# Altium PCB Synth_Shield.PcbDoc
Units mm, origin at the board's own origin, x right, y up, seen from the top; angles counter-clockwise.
Board outline 142 x 65.3 mm, 2 copper layers (TOP, BOTTOM), stack 1.5 mm thick; 26 components, 14 nets, 113 pads, 0 vias.
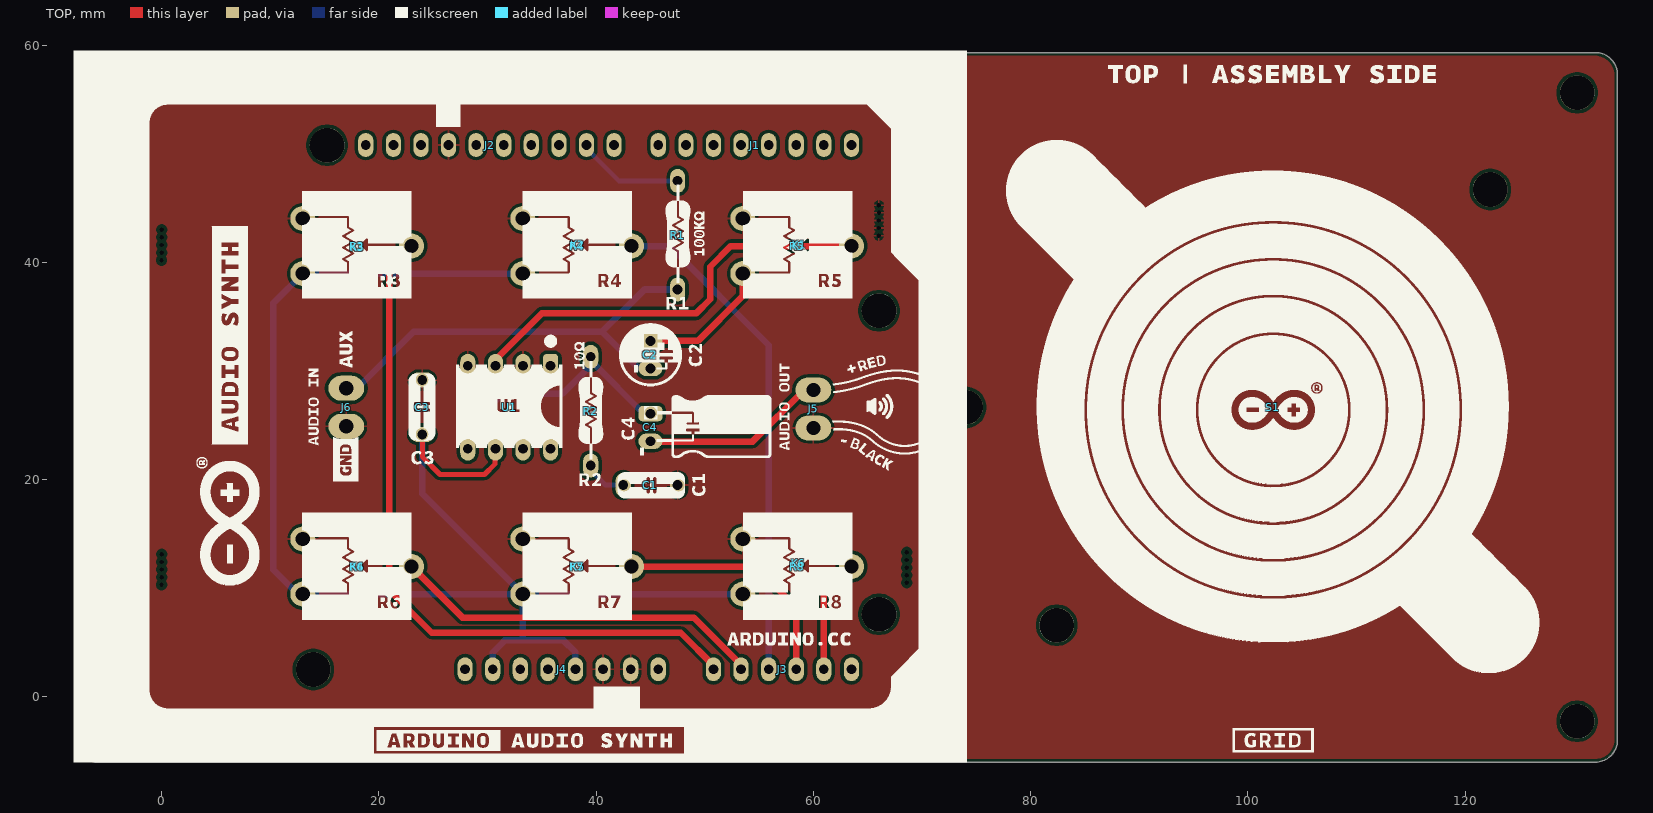
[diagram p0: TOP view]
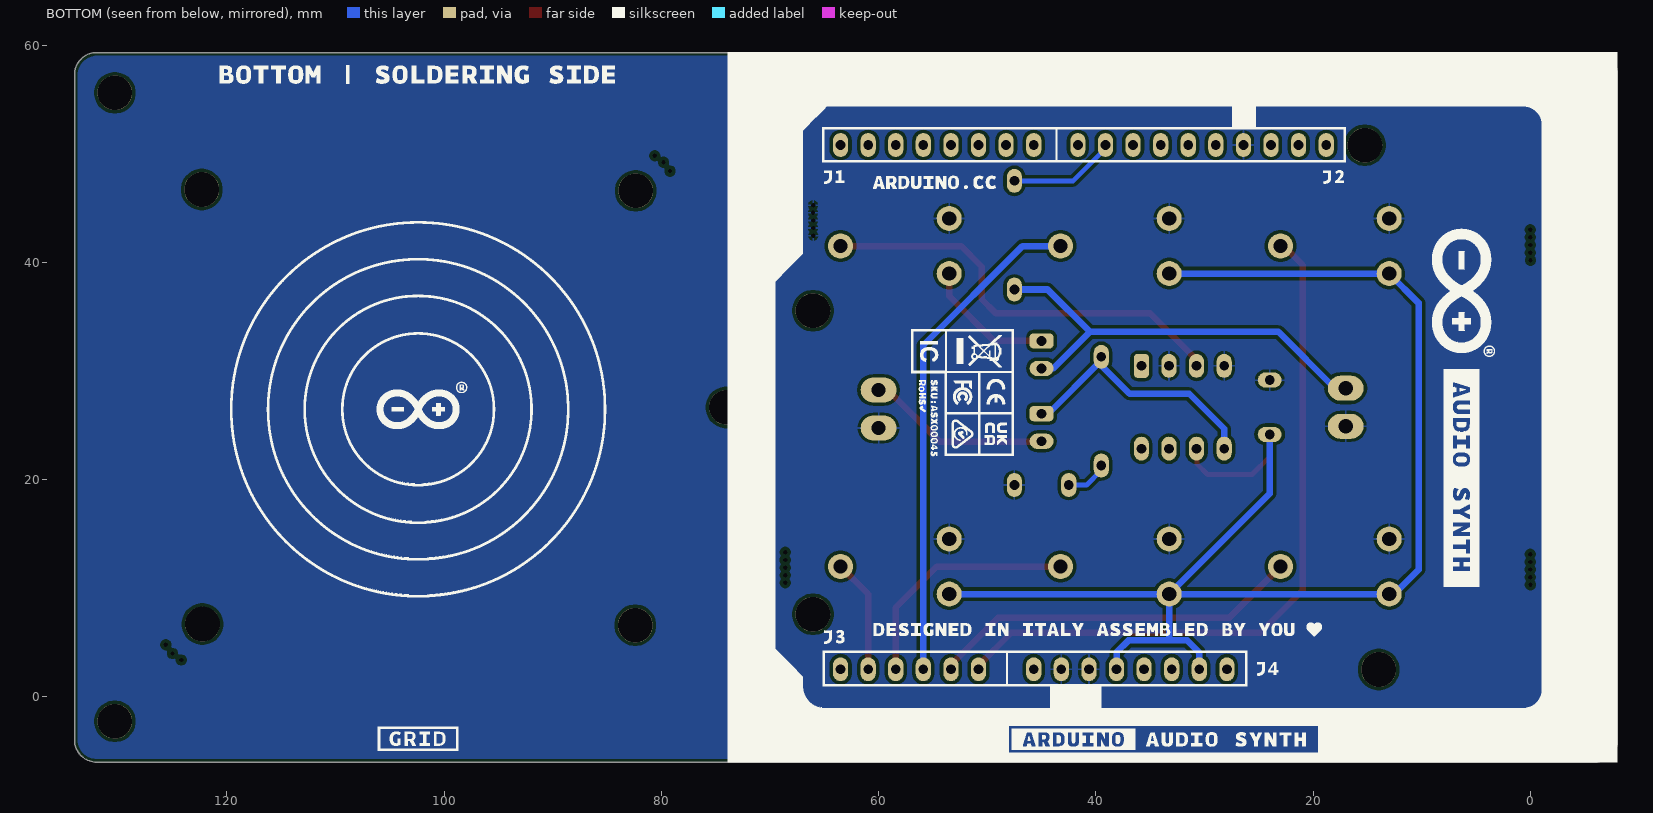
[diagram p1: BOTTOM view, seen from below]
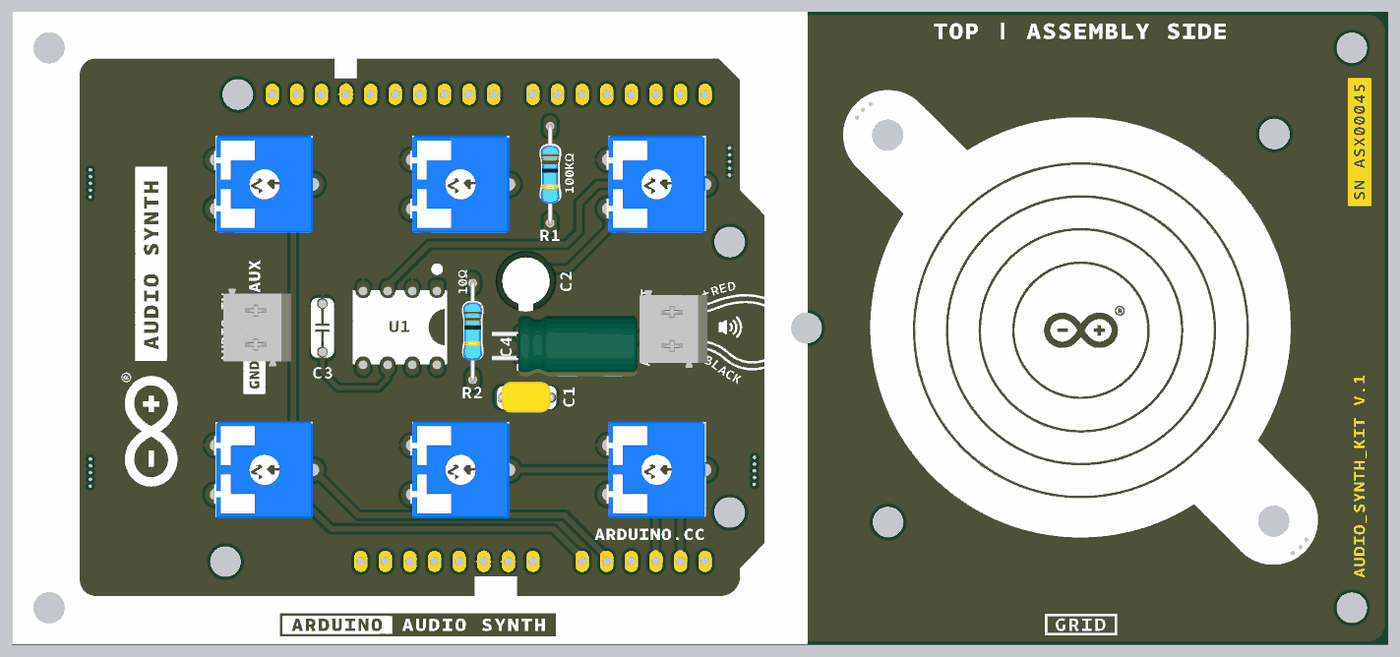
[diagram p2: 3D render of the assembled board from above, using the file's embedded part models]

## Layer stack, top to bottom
Top Solder: solder mask 0.0102, Solder Resist, Dk 3.5
TOP: signal copper 0.018
Dielectric2: core 1.464, FR-4, Dk 4.8
BOTTOM: signal copper 0.018
Bottom Solder: solder mask 0.0102, Solder Resist, Dk 3.5

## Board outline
-6,-6 cw(c-6,-4) -8,-4 -8,57.3 cw(c-6,57.3) -6,59.3 132,59.3 cw(c132,57.3) 134,57.3 134,-4 cw(c132,-4) 132,-6

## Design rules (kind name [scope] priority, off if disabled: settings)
BoardOutlineClearance Silks [(OnLayer('Top Overlay') OR OnLayer('Bottom Overlay'))] p1: gap=0 ignorepadtopadclearanceinfootprint=FALSE
BoardOutlineClearance [All] p2: gap=0.3 ignorepadtopadclearanceinfootprint=FALSE
Clearance COPPER_0.3mm [All] p1: gap=0.127 ignorepadtopadclearanceinfootprint=FALSE except(0.3: Arc-Fill Arc-Poly Arc-Region Track-Fill Track-Poly Track-Region SMDPad-Fill SMDPad-Poly SMDPad-Region THPad-Fill THPad-Poly THPad-Region Via-Fill Via-Poly Via-Region Fill-Fill Fill-Poly Fill-Region Poly-Poly Poly-Region Region-Region)
Clearance "Generic clearance 0.127mm" [All] p2: gap=0.127 ignorepadtopadclearanceinfootprint=FALSE
ComponentClearance [All] p1: gap=0.2 collisioncheckmode=3 verticalgap=0 showdistances=TRUE
DiffPairsRouting USB [InDifferentialPairClass('USB')] p1: maxlimit=0.15 minlimit=0.15 mostfreqgap=0.15 toplayer_minwidth=0.15 toplayer_maxwidth=0.21 toplayer_prefwidth=0.2 bottomlayer_minwidth=0.15 bottomlayer_maxwidth=0.21 bottomlayer_prefwidth=0.2 impedanceprofiledriven=TRUE impedanceprofileid={E6B00C31-4C8E-439C-824F-D2B2CDC26F9C} impedanceprofilevalue=90.000000 maxuncoupledlength=12.7
Height [All] p1: minheight=0 maxheight=30 prefheight=12.7
HoleSize [All] p1: absolutevalues=TRUE maxlimit=30 minlimit=0.3 maxpercent=80.000 minpercent=20.000
HoleToHoleClearance [All] p1: gap=0.25 allowstackedmicrovias=FALSE
MinimumAnnularRing [All] p1: minimumring=0.15
PlaneConnect [All] p1: pad.planeconnectstyle=Relief pad.reliefexpansion=0.508 pad.reliefentries=4 pad.reliefconductorwidth=0.254 pad.reliefairgap=0.254 via.planeconnectstyle=Direct via.reliefexpansion=0.508 via.reliefentries=4 via.reliefconductorwidth=0.254 via.reliefairgap=0.254
PolygonConnect [All] p1: thpad.connectstyle=Relief thpad.reliefconductorwidth=0.2 thpad.reliefentries=4 thpad.polygonreliefangle="90 Angle" thpad.airgapwidth=0.254 smdpad.connectstyle=Relief smdpad.reliefconductorwidth=0.2 smdpad.reliefentries=4 smdpad.polygonreliefangle="90 Angle" smdpad.airgapwidth=0.254 via.connectstyle=Direct via.reliefconductorwidth=0.254 via.reliefentries=4 via.polygonreliefangle="90 Angle" via.airgapwidth=0.254
RoomDefinition Synth_Audio_KIT [InComponentClass('Synth_Audio_KIT')] p1: confinementstyle=ConfineIn formatcopy=TRUE lockcomponents=FALSE outline -14.979,-6.4 195.1,-6.4 195.1,62.4 -14.979,62.4
RoutingVias StandardVias [All] p1: holewidth=0.3 width=0.6 viastyle="Through Hole" minholewidth=0.3 minwidth=0.6 maxholewidth=0.3 maxwidth=0.6
SMDToCorner [All] p1: distance=39370
SilkToSilkClearance [All] p1: silktosilkclearance=0.2
SilkToSolderMaskClearance [IsPad] p1: minsilkscreentomaskgap=0.15 clearancetoexposedcopper=TRUE
SolderMaskExpansion VIAtented [IsVia] p1: expansion=0.102 istentingtop=TRUE
SolderMaskExpansion [All] p2: expansion=0.05 istentingtop=FALSE
UnConnectedPin [All] p1:
UnRoutedNet [All] p1: checkbadconnections=TRUE
ViasUnderSMD [All] p1: allowed=FALSE
Width StandardTraces [All] p1: maxlimit=5 minlimit=0.127 preferedwidth=0.3
21 further rules are at their usual default settings.

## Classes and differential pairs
component class Synth_Audio_KIT: C1 C2 C3 C4 J2 J4 J5 J6 K1 K2 K3 K4 K5 K6 R1 R3 R4 R6 R7 R8 S1 U1

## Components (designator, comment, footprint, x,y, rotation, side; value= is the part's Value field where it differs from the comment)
C1 "TS170R1H473KSABB0R" TS170R1H473KSABB0R 45,19.5 r0 top value=47nF
C2 "EKF476M1EE05TU" EKF476M1EE05TU 45,31.5 r90 top value=47µF
C3 "B32529C0104J289" B32529C0104J289 24,26.661 r90 top value=100nF
C4 "EKM227M1EE11TUSAP" EKM227M1EE11TUSAP 45,24.8 r90 top value=220µF
J1 "PH1-08-UA" "CONN STRIP 2.54 PIN HEADER DIP 180° 1x 8 PIN GOLD FLASH" 54.61,50.8 r180 top
J2 "PH1-10-UA" "CONN STRIP 2.54 PIN HEADER DIP 180° 1x 10 PIN GOLD FLASH" 30.226,50.8 r180 top
J3 "PH1-06-UA" "2.54 PIN HEADER DIP 180° 1x 6 PIN GOLD FLASH" 57.15,2.54 r0 top
J4 "PH1-08-UA" "CONN STRIP 2.54 PIN HEADER DIP 180° 1x 8 PIN GOLD FLASH" 36.83,2.54 r0 top
J5 "MK125002GO" MK125002GO 60,26.5 r90 top
J6 "MK125002GO" MK125002GO 17,26.661 r90 top
K1 "KNOB TRIMMER" 0147 58.7,41.6 r0 top
K2 "KNOB TRIMMER" 0147 38.3,41.6 r0 top
K3 "KNOB TRIMMER" 0147 18,41.4 r0 top
K4 "KNOB TRIMMER" 0147 18,12 r0 top
K5 "KNOB TRIMMER" 0147 38.3,12 r0 top
K6 "KNOB TRIMMER" 0147 58.6,12.3 r0 top
R1 "1623930-1" -0-1623930-1 47.5,42.5 r270 top value=100K
R2 "1623930-5" R0230 39.5,26.3 r270 top value=10
R3 "CA9MV10-10KA2020" "New footprint 1" 23,41.5 r270 top
R4 "CA9MV10-10KA2020" "New footprint 1" 43.25,41.5 r270 top
R5 "CA9MV10-10KA2020" "New footprint 1" 63.5,41.5 r270 top
R6 "CA9MV10-10KA2020" "New footprint 1" 23,12 r270 top
R7 "CA9MV10-10KA2020" "New footprint 1" 43.25,12 r270 top
R8 "CA9MV10-10KA2020" "New footprint 1" 63.5,12 r270 top
S1 "L50EJ050008WLFLM-002" L50EJ050008WLFLM-002 102.3,26.64 r45 top
U1 "lm386" P0008A 32,26.661 r270 top

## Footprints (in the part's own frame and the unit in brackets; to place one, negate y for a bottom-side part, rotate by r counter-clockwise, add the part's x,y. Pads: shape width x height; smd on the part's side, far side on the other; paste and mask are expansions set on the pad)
"2.54 PIN HEADER DIP 180° 1x 6 PIN GOLD FLASH" [mm]
  oval 1.4x2.2 hole 0.9 mask+0.05: 1(-6.35,0) 2(-3.81,0) 3(-1.27,0) 4(1.27,0) 5(3.81,0) 6(6.35,0)
  body extent -7.67,-1.28 7.6,1.2, height 1.5
0147 [mm]
  body extent -4,-4 4,4, height 24.5
-0-1623930-1 [mm] "Axial Resistor, 2-Leads, Dia 2.4mm, Body Length 6.3mm"
  oval 2.2x1.4 hole 0.9 mask+0.05: 1(-5,0) 2(5,0)
  body extent -5.22,-1 5.23,1, height 1.8
B32529C0104J289 [mm]
  oval 1.4x2.2 hole 0.9 mask+0.05: 1(-2.5,0) 2(2.5,0)
  body extent -3.56,-1.27 3.56,1.27, height 6.5
"CONN STRIP 2.54 PIN HEADER DIP 180° 1x 8 PIN GOLD FLASH" [mm]
  oval 1.4x2.2 hole 0.9 mask+0.05: 1(-8.89,0) 2(-6.35,0) 3(-3.81,0) 4(-1.27,0) 5(1.27,0) 6(3.81,0) 7(6.35,0) 8(8.89,0)
  body extent -10.17,-1.18 10.18,1.3, height 1.5
"CONN STRIP 2.54 PIN HEADER DIP 180° 1x 10 PIN GOLD FLASH" [mm]
  oval 1.4x2.2 hole 0.9 mask+0.05: 1(-11.43,0) 2(-8.89,0) 3(-6.35,0) 4(-3.81,0) 5(-1.27,0) 6(1.27,0) 7(3.81,0) 8(6.35,0) 9(8.89,0) 10(11.43,0)
  body extent -12.67,-1.28 12.78,1.2, height 1.5
EKF476M1EE05TU [mm]
  oval 1.4x2.2 hole 0.9 mask+0.05: 1(-1.27,0)
  rrect50% 1.4x2.2 hole 0.9 mask+0.05: 2(1.27,0)
  body extent -3.15,-3.15 3.15,3.15, height 5.2
EKM227M1EE11TUSAP [mm]
  oval 1.4x2.2 hole 0.9 mask+0.05: 1(-1.27,0)
  rrect50% 1.4x2.2 hole 0.9 mask+0.05: 2(1.27,0)
  body extent -3.16,-11.5 3.15,3.5, height 6.15
L50EJ050008WLFLM-002 [mm]
  round 3.2 hole 3.2 unplated: ""(0,28.2) ""(0,-28.2)
MK125002GO [mm]
  oval 2.3x3.3 hole 1.3 mask+0.05: 1(-1.75,0) 2(1.75,0)
  body extent -3.95,-3.75 4.05,3.25, height 8.31
"New footprint 1" [mm]
  round 2.3 hole 1.3 mask+0.05: 1(-2.54,-10) 2(0,0) 3(2.54,-10)
  body extent -5,-10.2 5,0, height 6.35
P0008A [mm] "DIP, 8-Leads, Body 10.15x6.6mm, Pitch 2.54mm"
  rrect50% 2.2x1.4 hole 0.9 mask+0.05: 1(-3.81,3.81)
  oval 2.2x1.4 hole 0.9 mask+0.05: 2(-3.81,1.27) 3(-3.81,-1.27) 4(-3.81,-3.81) 5(3.81,-3.81) 6(3.81,-1.27) 7(3.81,1.27) 8(3.81,3.81)
  silkscreen extent -6.37,3.52 -5.78,4.12, body extent -3.95,-5.07 3.95,5.07, height 5.08
R0230 [mm] "Axial Resistor, 2-Leads, Dia 2.4mm, Body Length 6.3mm"
  oval 2.2x1.4 hole 0.9 mask+0.05: 1(-5,0) 2(5,0)
  body extent -5.22,-1 5.23,1, height 1.8
TS170R1H473KSABB0R [mm]
  oval 1.4x2.2 hole 0.9 mask+0.05: 1(-2.5,0) 2(2.5,0)
  body extent -2.79,-1.59 2.79,1.6, height 9.81

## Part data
C1: library part C0131-A.2, "CAP THD 47nF 50V C0G 5%", Manufacturer=Suntan, Package="P : 5.08 Ammo", Tolerance=5%, Voltage=50V
C2: library part C0125-A.8, "CAP ALUM POL THD 47uF 25V", Manufacturer=SAMXON, Package="6.3x5mm  P. 2.5mm", Tolerance=20%, Voltage=25V
C3: library part C0127-A.6, "CAP THD 100NF 63V POLIESTER", Manufacturer=EPCOS, Tolerance=5%, Voltage=63V
C4: library part C0129-A.1, "CAP ALUM POL THD 220uF 25V", Manufacturer="Man Yue Electronics Co.,Ltd", Package="6.3x11mm  P. 2.5mm", Tolerance=20%, Voltage=25V
J1: library part J0308-A.2, "CONN STRIP 2.54 PIN HEADER DIP 180° 1x 8 PIN GOLD FLASH", Manufacturer=4UCONN
J2: library part J0307-A.3, "CONN STRIP 2.54 PIN HEADER DIP 180° 1x 10 PIN GOLD FLASH", Manufacturer=4UCONN
J3: library part J0305-A.3, "CONN STRIP 2.54 PIN HEADER DIP 180° 1x 6 PIN GOLD FLASH", Manufacturer=4UCONN
J4: library part J0306-A.2, "CONN STRIP 2.54 PIN HEADER DIP 180° 1x 8 PIN GOLD FLASH", Manufacturer=4UCONN
J5 J6: library part J0012-A.7, "CONN MORS.CS 2v p3,5 10A aLING.VER", Manufacturer=Adimpex, Manufacturer 2="4U CON", Manufacturer Part Number 2=19TW-974
K1 K2 K3 K4 K5 K6: library part 0147-A.4, "KNOB TRIMMER ALBERINO.CA9 L23 D6/9mm", Manufacturer=T2, Part Number=9006
R1: library part R0231-A.3, "RES FIXED THD 1/4W 5% 100K", Manufacturer="TE connectivity", Power=330mW, Tolerance=5%
R2: library part R0230-A.2, "RES FIXED THD 1/4W 5% 10R", Manufacturer="TE connectivity", Power=330mW, Tolerance=5%
R3 R4 R5 R6 R7 R8: library part 0086-2, "Potentiometer 10kilohm - TRIMMER", Value max=10K, Value min=0
S1: library part S0025-A.7, "Paper Speaker 8Ω 1W + Grid  PCB", Manufacturer="DB Pructs Limited"
U1: library part U0251-A.1, "Audio Amplifier, 0.325W, 1 Channel(s), 1 Func, Bipolar, PDIP8", Max Operating Temperature=70°C, Min Operating Temperature=0°C, Part Number=LM386N-1/NOPB

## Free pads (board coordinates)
  round 0 hole 0.4 unplated: MOUSEBITES(-0.001,40.195) MOUSEBITES(0,10.322) MOUSEBITES(0.011,42.995) MOUSEBITES(0.011,13.122) MOUSEBITES(0.012,40.895) MOUSEBITES(0.012,41.595) MOUSEBITES(0.013,11.022) MOUSEBITES(0.013,11.722) MOUSEBITES(0.017,42.295) MOUSEBITES(0.017,12.422) MOUSEBITES(66.017,42.453) MOUSEBITES(66.028,45.253) MOUSEBITES(66.03,43.153) MOUSEBITES(66.03,43.853) MOUSEBITES(66.034,44.553) MOUSEBITES(68.589,10.5) MOUSEBITES(68.6,13.3) MOUSEBITES(68.601,11.2) MOUSEBITES(68.601,11.9) MOUSEBITES(68.606,12.6) MOUSEBITES(79.2,48.4) MOUSEBITES(79.8,49.2) MOUSEBITES(80.6,49.8) MOUSEBITES(124.2,3.4) MOUSEBITES(125,4) MOUSEBITES(125.6,4.8)
  round 0 hole 3.2 unplated: ""(-4.25,-2.25) ""(-4.25,55.6)
  round 3.2 hole 3.2 unplated: ""(13.969,2.522) ""(15.239,50.782) ""(66.039,7.602) ""(66.039,35.542) ""(74,26.65) ""(82.4,6.6) ""(122.3,46.7) ""(130.3,-2.25) ""(130.3,55.6)

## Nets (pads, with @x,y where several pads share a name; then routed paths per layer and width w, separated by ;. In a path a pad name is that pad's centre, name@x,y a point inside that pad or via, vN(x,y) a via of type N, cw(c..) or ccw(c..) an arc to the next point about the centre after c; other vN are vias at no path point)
+5V: C3.1 J4.2 J4.5 R3.3 R4.3 R6.3 R7.3 R8.3 U1.6 | length 138.4
  TOP w0.45: C3.1 24,22.1 25.633,20.467 29.724,20.467 30.686,21.428 U1.6@30.686,22.807
  BOTTOM w0.6: C3.1 24,18.71 R7.3 ; J4.2 30.48,4.08 31.6,5.2 33.25,5.2 ; R4.3 R3.3 10.3,36.26 10.3,11.7 12.54,9.46 R6.3 R7.3 ; J4.5 38.1,4.1 37,5.2 33.25,5.2 ; R8.3 R7.3 ; 33.25,5.2 R7.3
AD0_1: J3.1 R3.2 | length 65.8
  TOP w0.6: R3.2 22.7,41.5 20.954,39.754 20.954,9.816 24.866,5.904 47.796,5.904 50.8,2.9 J3.1
AD1_1: J3.2 R6.2 | length 34.5
  TOP w0.6: R6.2 27.696,7.304 48.996,7.304 53.34,2.96 J3.2
AD2_1: J3.3 R4.2 | length 46.2
  BOTTOM w0.6: R4.2 46.75,41.5 55.88,32.37 J3.3
AD3_1: J3.4 R7.2 | length 22.4
  TOP w0.6: R7.2 54.637,12 58.42,8.217 J3.4
AD4/SDA_1: J3.5 R8.2 | length 10.5
  TOP w0.6: J3.5 60.96,9.46 R8.2
AUX/IN_1: C2.1 J6.2 R1.2 | length 41.1
  BOTTOM w0.6: J6.2@16,28.411 J6.2 18.011,28.411 23.2,33.6 40.493,33.6 ; 40.547,33.6 43.917,30.23 C2.1 ; 40.552,33.6 44.452,37.5 R1.2
GND: C1.2 C3.2 J2.7 J4.6 J4.7 J5.1 J6.1 pad.MOUSEBITES@66.03,43.153 pad.MOUSEBITES@66.03,43.853 pad.MOUSEBITES@66.017,42.453 pad.MOUSEBITES@66.028,45.253 pad.MOUSEBITES@66.034,44.553 R3.1 R4.1 R5.1 R6.1 R7.1 R8.1 U1.2 U1.4
NetC1_1: C1.1 R2.2 | length 4
  BOTTOM w0.45: R2.2 39.5,20.848 40.848,19.5 C1.1
NetC2_2: C2.2 R5.3 | length 12.3
  TOP w0.6: C2.2 49.37,32.77 53.5,36.9 R5.3
NetC4_1: C4.1 J5.2 | length 17
  TOP w0.6: C4.1@45,23.5 54.4,23.5 59.15,28.25 J5.2
NetC4_2: C4.2 R2.1 U1.5 | length 23.1
  BOTTOM w0.6: U1.5 28.19,24.679 31.411,27.9 36.9,27.9 39.728,30.728 44.386,26.07 C4.2
NetJ2_2: J2.2 R1.1 | length 9.9
  BOTTOM w0.3: J2.2@39.1,50.784 J2.2
  BOTTOM w0.45: J2.2@39.1,50.784 39.1,50.5 42.1,47.5 R1.1
NetR5_2: R5.2 U1.3 | length 39.4
  TOP w0.6: U1.3 30.73,31.034 34.996,35.3 49.2,35.3 50.5,36.6 50.5,39.6 52.4,41.5 R5.2
pads on no net: J1.1 J1.2 J1.3 J1.4 J1.5 J1.6 J1.7 J1.8 J2.1 J2.3 J2.4 J2.5 J2.6 J2.8 J2.9 J2.10 J3.6 J4.1 J4.3 J4.4 J4.8 S1. U1.1 U1.7 U1.8

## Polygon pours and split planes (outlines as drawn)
GND on BOTTOM "NONET_L-01_P-001" (solid, pour order 1): -8,-6 134,-6 134,59.3 -8,59.3
GND on TOP "NONET_L-01_P-001" (solid, pour order 0): -8,-6 134,-6 134,59.3 -8,59.3

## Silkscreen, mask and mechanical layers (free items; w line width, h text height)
Top Overlay:
  drawing of 158 lines, arcs and shapes, not listed
Bottom Overlay:
  drawing of 140 lines, arcs and shapes, not listed
Top Solder:
  drawing of 27 lines, arcs and shapes, not listed
Bottom Solder:
  drawing of 27 lines, arcs and shapes, not listed
Top Designator:
  lines w0.254: 64.718,53.119 66.039,51.798 66.039,40.368 ; 64.914,0 ccw(c64.914,1.102) 66.016,1.102 66.039,2.522 68.579,5.062 68.579,37.828 66.107,40.3 ; 74.094,58.3 74.094,59.2 ; 98.1,26.65 106.3,26.65 ; 102.249,22.4 102.249,30.8
Route Tool Path:
  lines w2: -1,10.1 -1,1.038 ccw(c-0.002,0.98) -1.002,0.98 ccw(c0.98,0.98) 0.98,-1.002 ; -1,13.3 -1,40.1 ; -1,43.104 -1,52.3 ; 0.98,-1 65.678,-1 67.1,0.421 67.126,2.029 69.681,4.584 69.681,10.6 ; 65.4,-1 65.627,-1.004 ; 67.074,45.329 67.074,52.281 65.034,54.322 0.999,54.322 ccw(c0.999,52.322) -1.001,52.322 ; 67.141,42.57 67.141,40.784 69.681,38.244 69.681,30.1 ; 69.7,13.6 69.7,30.7 ; 80.488,50.927 cw(c82.3,47.37) 85.22,50.093 ; 119.09,3.546 ccw(c122.3,6.7) 123.839,2.471 ; -1.001,52.322 ccw(c-0.001,52.322) -1,52.283 cw(c-0.001,52.322) -1.001,52.322 ; 0.98,-1.002 ccw(c0.98,-0.002) 1.038,-1 cw(c0.98,-0.002) 0.98,-1.002
Board:
  the board outline again, w0.1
